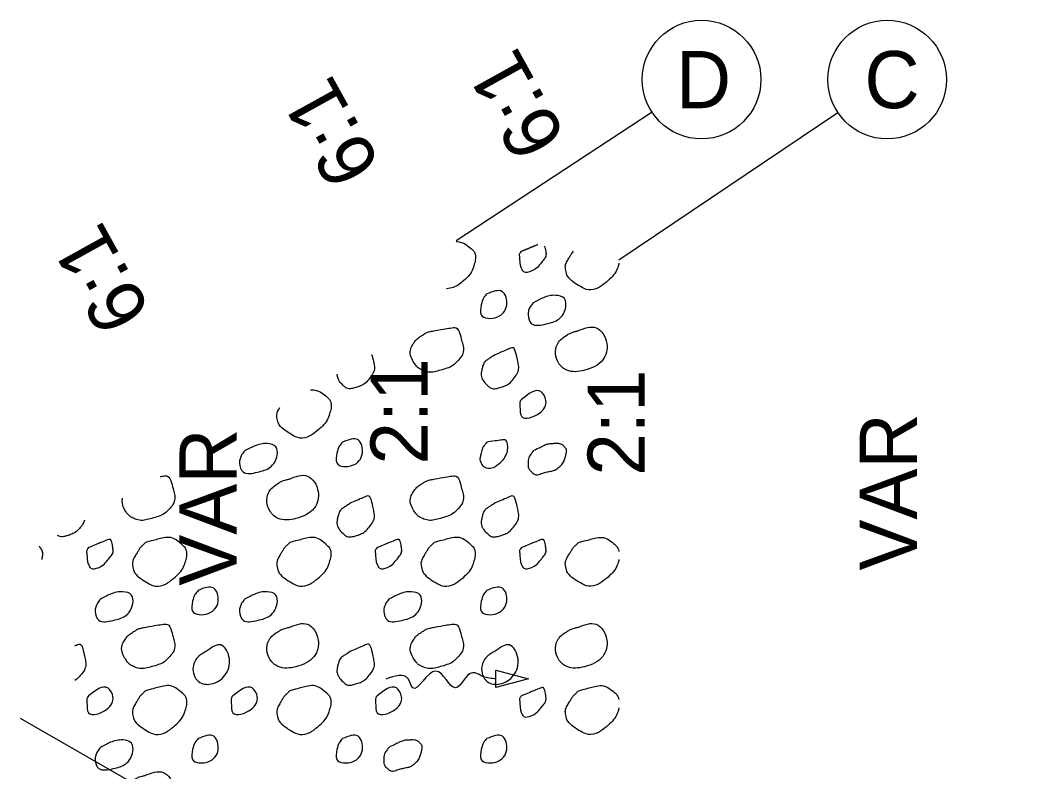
# Model space of a CAD drawing. Extents: x 0 to 2278, y -264 to 330.
# Drawn here: x 275.97 to 313.29, y 222.49 to 250.09 of the extents above; entities that cross this region are included whole.
import ezdxf

# ---------------------------------------------------------------- set-up
doc = ezdxf.new("R2010")
doc.units = 0
for name, color, linetype in [('DR_P_Culvert', 7, 'Continuous'), ('TX_X_10', 7, 'Continuous'), ('XS_P_Finished_Grade', 7, 'Continuous')]:
    doc.layers.add(name, color=color, linetype=linetype)

msp = doc.modelspace()

# ---------------------------------------------------------------- linework, layer by layer
at = {"layer": 'DR_P_Culvert'}
msp.add_line((275.975, 224.45), (325.671, 195.939), dxfattribs=at)
for centre in [(301.013, 247.915), (307.834, 247.915)]:
    msp.add_circle(centre, 2.179, dxfattribs=at)
at = {"layer": 'TX_X_10'}
for p, q in [((299.192, 246.717), (291.996, 241.985)), ((306.026, 246.698), (297.975, 241.284)), ((293.453, 226.221), (294.654, 225.903)), ((293.455, 225.577), (293.453, 226.221)), ((294.654, 225.903), (293.455, 225.577))]:
    msp.add_line(p, q, dxfattribs=at)
msp.add_spline([(293.456, 225.902), (293.408, 225.902), (292.914, 226.013), (292.601, 226.121), (291.967, 225.567), (291.237, 226.184), (290.399, 225.562), (290.228, 225.897), (289.404, 225.885)], degree=3, dxfattribs=at)
at = {"layer": 'XS_P_Finished_Grade'}
for points, degree in [([(291.99, 241.965), (292.16, 241.953), (292.331, 241.883), (292.501, 241.741), (292.703, 241.573), (292.716, 241.324), (292.662, 241.138), (292.595, 240.903), (292.446, 240.68), (292.218, 240.485), (292.05, 240.341), (291.842, 240.249), (291.641, 240.233)], 3), ([(294.391, 241.61), (294.592, 241.692), (294.793, 241.777), (294.994, 241.857)], 2), ([(295.23, 241.811), (295.266, 241.736), (295.287, 241.632), (295.292, 241.571), (295.306, 241.422), (295.192, 241.266), (295.068, 241.118), (294.901, 240.916), (294.48, 240.77), (294.393, 240.991), (294.347, 241.109), (294.34, 241.23), (294.335, 241.351), (294.332, 241.412), (294.31, 241.479), (294.341, 241.533), (294.357, 241.56), (294.375, 241.584), (294.391, 241.61)], 3), ([(297.975, 241.172), (297.972, 241.16), (297.969, 241.149), (297.966, 241.138), (297.899, 240.903), (297.75, 240.68), (297.522, 240.485), (297.237, 240.242), (296.841, 240.146), (296.55, 240.319), (296.313, 240.459), (296.064, 240.669), (296.018, 240.916), (295.99, 241.071), (296.07, 241.25), (296.161, 241.394), (296.207, 241.467), (296.249, 241.54), (296.3, 241.606)], 3), ([(291.155, 238.681), (291.382, 238.72), (291.609, 238.763), (291.836, 238.794), (292.063, 238.826), (292.168, 238.437), (292.225, 238.224), (292.276, 238.031), (292.243, 237.795), (292.08, 237.614), (291.88, 237.393), (291.658, 237.308), (291.411, 237.236), (291.199, 237.173), (290.962, 237.151), (290.751, 237.239), (290.623, 237.293), (290.53, 237.387), (290.452, 237.507), (290.323, 237.708), (290.284, 237.985), (290.397, 238.174), (290.472, 238.3), (290.574, 238.411), (290.705, 238.494), (290.815, 238.565), (290.921, 238.631), (291.043, 238.657), (291.085, 238.666), (291.126, 238.674), (291.167, 238.683)], 3), ([(293.428, 237.807), (293.604, 237.882), (293.78, 237.958), (293.956, 238.033), (294.138, 238.111), (294.227, 237.711), (294.267, 237.526), (294.31, 237.329), (294.259, 237.109), (294.1, 236.918), (293.95, 236.739), (293.779, 236.654), (293.6, 236.599), (293.456, 236.556), (293.274, 236.549), (293.133, 236.688), (292.963, 236.857), (292.899, 237.055), (292.933, 237.227), (292.961, 237.363), (293.024, 237.543), (293.152, 237.628), (293.244, 237.689), (293.337, 237.747), (293.428, 237.807)], 3), ([(288.884, 237.82), (288.921, 237.718), (288.947, 237.603), (288.963, 237.526), (289.006, 237.329), (288.955, 237.109), (288.796, 236.918), (288.646, 236.739), (288.476, 236.654), (288.296, 236.599), (288.152, 236.556), (287.971, 236.549), (287.83, 236.688), (287.702, 236.814), (287.635, 236.956), (287.623, 237.092)], 3), ([(286.635, 236.522), (286.822, 236.52), (287.01, 236.452), (287.197, 236.296), (287.399, 236.127), (287.412, 235.878), (287.358, 235.692), (287.291, 235.457), (287.143, 235.234), (286.915, 235.039), (286.63, 234.796), (286.234, 234.7), (285.942, 234.873), (285.706, 235.013), (285.457, 235.223), (285.411, 235.471), (285.387, 235.598), (285.438, 235.743), (285.508, 235.871)], 3), ([(293.122, 234.594), (293.313, 234.621), (293.504, 234.652), (293.695, 234.677), (293.865, 234.7), (293.905, 234.332), (293.851, 234.185), (293.792, 234.022), (293.644, 233.861), (293.491, 233.744), (293.334, 233.623), (293.002, 233.643), (292.911, 233.829), (292.854, 233.945), (292.882, 234.081), (292.915, 234.197), (292.938, 234.28), (292.948, 234.374), (293.002, 234.442), (293.042, 234.493), (293.082, 234.543), (293.122, 234.594)], 3), ([(294.828, 234.269), (294.953, 234.332), (295.078, 234.394), (295.203, 234.456), (295.341, 234.525), (295.505, 234.538), (295.655, 234.542), (295.765, 234.546), (295.871, 234.52), (295.971, 234.421), (296.062, 234.331), (296.049, 234.211), (296.022, 234.116), (295.978, 233.959), (295.919, 233.798), (295.766, 233.671), (295.616, 233.546), (295.457, 233.529), (295.296, 233.491), (295.127, 233.452), (294.934, 233.352), (294.768, 233.5), (294.659, 233.598), (294.637, 233.712), (294.64, 233.824), (294.642, 233.923), (294.655, 234.041), (294.717, 234.124), (294.754, 234.173), (294.791, 234.221), (294.828, 234.269)], 3), ([(281.109, 233.331), (281.149, 233.337), (281.189, 233.343), (281.229, 233.349), (281.455, 233.38), (281.56, 232.991), (281.617, 232.779), (281.669, 232.585), (281.635, 232.349), (281.472, 232.169), (281.272, 231.947), (281.05, 231.862), (280.804, 231.79), (280.592, 231.728), (280.354, 231.705), (280.144, 231.794), (280.015, 231.848), (279.922, 231.941), (279.845, 232.061), (279.755, 232.2), (279.709, 232.375), (279.726, 232.533)], 3), ([(291.155, 233.235), (291.382, 233.274), (291.609, 233.317), (291.836, 233.349), (292.063, 233.38), (292.168, 232.991), (292.225, 232.779), (292.276, 232.585), (292.243, 232.349), (292.08, 232.169), (291.88, 231.947), (291.658, 231.862), (291.411, 231.79), (291.199, 231.728), (290.962, 231.705), (290.751, 231.794), (290.623, 231.848), (290.53, 231.941), (290.452, 232.061), (290.323, 232.262), (290.284, 232.539), (290.397, 232.729), (290.472, 232.854), (290.574, 232.966), (290.705, 233.049), (290.815, 233.119), (290.921, 233.185), (291.043, 233.211), (291.085, 233.22), (291.126, 233.229), (291.167, 233.237)], 3), ([(288.125, 232.361), (288.301, 232.437), (288.476, 232.512), (288.652, 232.587), (288.835, 232.666), (288.923, 232.266), (288.963, 232.08), (289.006, 231.883), (288.955, 231.663), (288.796, 231.472), (288.646, 231.293), (288.476, 231.208), (288.296, 231.154), (288.152, 231.11), (287.971, 231.103), (287.83, 231.242), (287.659, 231.411), (287.595, 231.609), (287.63, 231.781), (287.657, 231.918), (287.721, 232.098), (287.848, 232.182), (287.94, 232.244), (288.033, 232.301), (288.125, 232.361)], 3), ([(293.428, 232.361), (293.604, 232.437), (293.78, 232.512), (293.956, 232.587), (294.138, 232.666), (294.227, 232.266), (294.267, 232.08), (294.31, 231.883), (294.259, 231.663), (294.1, 231.472), (293.95, 231.293), (293.779, 231.208), (293.6, 231.154), (293.456, 231.11), (293.274, 231.103), (293.133, 231.242), (292.963, 231.411), (292.899, 231.609), (292.933, 231.781), (292.961, 231.918), (293.024, 232.098), (293.152, 232.182), (293.244, 232.244), (293.337, 232.301), (293.428, 232.361)], 3), ([(278.334, 231.729), (278.305, 231.641), (278.257, 231.554), (278.189, 231.472), (278.039, 231.293), (277.868, 231.208), (277.689, 231.154), (277.584, 231.122), (277.46, 231.11), (277.346, 231.159)], 3), ([(278.48, 230.719), (278.717, 230.815), (278.955, 230.917), (279.192, 231.007), (279.309, 231.052), (279.37, 230.792), (279.381, 230.68), (279.395, 230.531), (279.281, 230.374), (279.157, 230.226), (278.99, 230.025), (278.569, 229.879), (278.482, 230.1), (278.436, 230.218), (278.428, 230.339), (278.424, 230.46), (278.421, 230.52), (278.398, 230.587), (278.43, 230.641), (278.446, 230.669), (278.463, 230.693), (278.48, 230.719)], 3), ([(280.579, 230.907), (280.756, 230.955), (280.934, 231.001), (281.112, 231.047), (281.372, 231.115), (281.634, 231.067), (281.894, 230.85), (282.095, 230.681), (282.108, 230.432), (282.055, 230.246), (281.987, 230.011), (281.839, 229.788), (281.611, 229.594), (281.326, 229.35), (280.93, 229.255), (280.639, 229.427), (280.402, 229.567), (280.153, 229.777), (280.107, 230.025), (280.079, 230.179), (280.159, 230.359), (280.25, 230.502), (280.314, 230.605), (280.372, 230.709), (280.457, 230.791), (280.498, 230.83), (280.538, 230.869), (280.579, 230.907)], 3), ([(285.882, 230.907), (286.06, 230.955), (286.238, 231.001), (286.416, 231.047), (286.676, 231.115), (286.937, 231.067), (287.197, 230.85), (287.399, 230.681), (287.412, 230.432), (287.358, 230.246), (287.291, 230.011), (287.143, 229.788), (286.915, 229.594), (286.63, 229.35), (286.234, 229.255), (285.942, 229.427), (285.706, 229.567), (285.457, 229.777), (285.411, 230.025), (285.383, 230.179), (285.463, 230.359), (285.553, 230.502), (285.618, 230.605), (285.676, 230.709), (285.761, 230.791), (285.801, 230.83), (285.842, 230.869), (285.882, 230.907)], 3), ([(289.087, 230.719), (289.325, 230.815), (289.562, 230.917), (289.8, 231.007), (289.916, 231.052), (289.978, 230.792), (289.988, 230.68), (290.003, 230.531), (289.888, 230.374), (289.765, 230.226), (289.597, 230.025), (289.177, 229.879), (289.09, 230.1), (289.044, 230.218), (289.036, 230.339), (289.031, 230.46), (289.029, 230.52), (289.006, 230.587), (289.037, 230.641), (289.053, 230.669), (289.071, 230.693), (289.087, 230.719)], 3), ([(291.186, 230.907), (291.364, 230.955), (291.542, 231.001), (291.72, 231.047), (291.98, 231.115), (292.241, 231.067), (292.501, 230.85), (292.703, 230.681), (292.716, 230.432), (292.662, 230.246), (292.595, 230.011), (292.446, 229.788), (292.218, 229.594), (291.933, 229.35), (291.538, 229.255), (291.246, 229.427), (291.01, 229.567), (290.76, 229.777), (290.715, 230.025), (290.686, 230.179), (290.767, 230.359), (290.857, 230.502), (290.922, 230.605), (290.979, 230.709), (291.065, 230.791), (291.105, 230.83), (291.145, 230.869), (291.186, 230.907)], 3), ([(294.391, 230.719), (294.629, 230.815), (294.866, 230.917), (295.103, 231.007), (295.22, 231.052), (295.282, 230.792), (295.292, 230.68), (295.306, 230.531), (295.192, 230.374), (295.068, 230.226), (294.901, 230.025), (294.48, 229.879), (294.393, 230.1), (294.347, 230.218), (294.34, 230.339), (294.335, 230.46), (294.332, 230.52), (294.31, 230.587), (294.341, 230.641), (294.357, 230.669), (294.375, 230.693), (294.391, 230.719)], 3), ([(296.49, 230.907), (296.667, 230.955), (296.846, 231.001), (297.023, 231.047), (297.283, 231.115), (297.545, 231.067), (297.805, 230.85), (297.897, 230.773), (297.95, 230.678), (297.975, 230.581)], 3), ([(276.669, 230.768), (276.784, 230.619), (276.795, 230.435), (276.761, 230.284)], 2), ([(297.975, 230.281), (297.972, 230.269), (297.969, 230.258), (297.966, 230.246), (297.899, 230.011), (297.75, 229.788), (297.522, 229.594), (297.237, 229.35), (296.841, 229.255), (296.55, 229.427), (296.313, 229.567), (296.064, 229.777), (296.018, 230.025), (295.99, 230.179), (296.07, 230.359), (296.161, 230.502), (296.226, 230.605), (296.283, 230.709), (296.368, 230.791), (296.409, 230.83), (296.449, 230.869), (296.49, 230.907)], 3), ([(280.547, 227.789), (280.774, 227.828), (281.002, 227.871), (281.229, 227.903), (281.455, 227.935), (281.56, 227.546), (281.617, 227.333), (281.669, 227.14), (281.635, 226.903), (281.472, 226.723), (281.272, 226.502), (281.05, 226.417), (280.804, 226.344), (280.592, 226.282), (280.354, 226.259), (280.144, 226.348), (280.015, 226.402), (279.922, 226.495), (279.845, 226.615), (279.715, 226.816), (279.677, 227.093), (279.79, 227.283), (279.865, 227.409), (279.967, 227.52), (280.097, 227.603), (280.208, 227.673), (280.313, 227.739), (280.436, 227.765), (280.477, 227.774), (280.519, 227.783), (280.56, 227.792)], 3), ([(291.155, 227.789), (291.382, 227.828), (291.609, 227.871), (291.836, 227.903), (292.063, 227.935), (292.168, 227.546), (292.225, 227.333), (292.276, 227.14), (292.243, 226.903), (292.08, 226.723), (291.88, 226.502), (291.658, 226.417), (291.411, 226.344), (291.199, 226.282), (290.962, 226.259), (290.751, 226.348), (290.623, 226.402), (290.53, 226.495), (290.452, 226.615), (290.323, 226.816), (290.284, 227.093), (290.397, 227.283), (290.472, 227.409), (290.574, 227.52), (290.705, 227.603), (290.815, 227.673), (290.921, 227.739), (291.043, 227.765), (291.085, 227.774), (291.126, 227.783), (291.167, 227.792)], 3), ([(277.975, 227.112), (277.998, 227.122), (278.021, 227.132), (278.045, 227.142), (278.227, 227.22), (278.316, 226.82), (278.356, 226.634), (278.398, 226.438), (278.347, 226.217), (278.189, 226.027), (278.121, 225.946), (278.05, 225.884), (277.975, 225.836)], 3), ([(288.125, 226.915), (288.301, 226.991), (288.476, 227.066), (288.652, 227.142), (288.835, 227.22), (288.923, 226.82), (288.963, 226.634), (289.006, 226.438), (288.955, 226.217), (288.796, 226.027), (288.646, 225.847), (288.476, 225.762), (288.296, 225.708), (288.152, 225.664), (287.971, 225.657), (287.83, 225.797), (287.659, 225.965), (287.595, 226.164), (287.63, 226.335), (287.657, 226.472), (287.721, 226.652), (287.848, 226.737), (287.94, 226.798), (288.033, 226.856), (288.125, 226.915)], 3), ([(280.579, 225.462), (280.756, 225.509), (280.934, 225.556), (281.112, 225.602), (281.372, 225.669), (281.634, 225.621), (281.894, 225.404), (282.095, 225.236), (282.108, 224.987), (282.055, 224.8), (281.987, 224.565), (281.839, 224.343), (281.611, 224.148), (281.326, 223.905), (280.93, 223.809), (280.639, 223.982), (280.402, 224.122), (280.153, 224.332), (280.107, 224.579), (280.079, 224.734), (280.159, 224.913), (280.25, 225.057), (280.314, 225.159), (280.372, 225.263), (280.457, 225.345), (280.498, 225.384), (280.538, 225.423), (280.579, 225.462)], 3), ([(285.882, 225.462), (286.06, 225.509), (286.238, 225.556), (286.416, 225.602), (286.676, 225.669), (286.937, 225.621), (287.197, 225.404), (287.399, 225.236), (287.412, 224.987), (287.358, 224.8), (287.291, 224.565), (287.143, 224.343), (286.915, 224.148), (286.63, 223.905), (286.234, 223.809), (285.942, 223.982), (285.706, 224.122), (285.457, 224.332), (285.411, 224.579), (285.383, 224.734), (285.463, 224.913), (285.553, 225.057), (285.618, 225.159), (285.676, 225.263), (285.761, 225.345), (285.801, 225.384), (285.842, 225.423), (285.882, 225.462)], 3), ([(294.391, 225.273), (294.629, 225.369), (294.866, 225.471), (295.103, 225.562), (295.22, 225.606), (295.282, 225.346), (295.292, 225.234), (295.306, 225.085), (295.192, 224.929), (295.068, 224.78), (294.901, 224.579), (294.48, 224.433), (294.393, 224.654), (294.347, 224.772), (294.34, 224.893), (294.335, 225.014), (294.332, 225.075), (294.31, 225.141), (294.341, 225.195), (294.357, 225.223), (294.375, 225.247), (294.391, 225.273)], 3), ([(297.975, 224.835), (297.972, 224.823), (297.969, 224.812), (297.966, 224.8), (297.899, 224.565), (297.75, 224.343), (297.522, 224.148), (297.237, 223.905), (296.841, 223.809), (296.55, 223.982), (296.313, 224.122), (296.064, 224.332), (296.018, 224.579), (295.99, 224.734), (296.07, 224.913), (296.161, 225.057), (296.226, 225.159), (296.283, 225.263), (296.368, 225.345), (296.409, 225.384), (296.449, 225.423), (296.49, 225.462)], 3), ([(296.49, 225.462), (296.667, 225.509), (296.846, 225.556), (297.023, 225.602), (297.283, 225.669), (297.545, 225.621), (297.805, 225.404), (297.897, 225.327), (297.95, 225.233), (297.975, 225.135)], 3), ([(289.525, 223.377), (289.65, 223.44), (289.774, 223.502), (289.9, 223.565), (290.037, 223.633), (290.201, 223.647), (290.351, 223.651), (290.461, 223.654), (290.568, 223.628), (290.667, 223.53), (290.758, 223.44), (290.745, 223.32), (290.718, 223.225), (290.674, 223.067), (290.615, 222.907), (290.462, 222.78), (290.312, 222.655), (290.153, 222.637), (289.992, 222.6), (289.823, 222.56), (289.63, 222.46), (289.465, 222.608), (289.356, 222.706), (289.333, 222.821), (289.336, 222.932), (289.339, 223.032), (289.351, 223.149), (289.413, 223.232), (289.45, 223.281), (289.487, 223.329), (289.525, 223.377)], 3)]:
    msp.add_open_spline(points, degree=degree, dxfattribs=at)
for points in [[(293.122, 240.039), (293.695, 240.123), (293.851, 239.631), (293.491, 239.189), (292.911, 239.274), (292.915, 239.643), (293.002, 239.888), (293.122, 240.039)], [(294.828, 239.714), (295.203, 239.902), (295.655, 239.988), (295.971, 239.867), (296.022, 239.562), (295.766, 239.117), (295.296, 238.937), (294.768, 238.946), (294.64, 239.269), (294.717, 239.569), (294.828, 239.714)], [(296.458, 238.681), (297.14, 238.794), (297.528, 238.224), (297.383, 237.614), (296.715, 237.236), (296.055, 237.239), (295.756, 237.507), (295.701, 238.174), (296.008, 238.494), (296.347, 238.657), (296.471, 238.683)], [(294.391, 236.164), (295.103, 236.453), (295.292, 236.126), (295.068, 235.672), (294.393, 235.546), (294.335, 235.906), (294.341, 236.087), (294.391, 236.164)], [(287.818, 234.594), (288.391, 234.677), (288.547, 234.185), (288.187, 233.744), (287.607, 233.829), (287.611, 234.197), (287.698, 234.442), (287.818, 234.594)], [(284.221, 234.269), (284.596, 234.456), (285.047, 234.542), (285.363, 234.421), (285.415, 234.116), (285.158, 233.671), (284.688, 233.491), (284.161, 233.5), (284.032, 233.824), (284.11, 234.124), (284.221, 234.269)], [(285.851, 233.235), (286.532, 233.349), (286.921, 232.779), (286.776, 232.169), (286.107, 231.79), (285.447, 231.794), (285.148, 232.061), (285.093, 232.729), (285.401, 233.049), (285.74, 233.211), (285.863, 233.237)], [(282.515, 229.148), (283.087, 229.232), (283.244, 228.739), (282.884, 228.298), (282.304, 228.383), (282.307, 228.752), (282.395, 228.997), (282.515, 229.148)], [(293.122, 229.148), (293.695, 229.232), (293.851, 228.739), (293.491, 228.298), (292.911, 228.383), (292.915, 228.752), (293.002, 228.997), (293.122, 229.148)], [(278.917, 228.823), (279.292, 229.01), (279.744, 229.097), (280.06, 228.975), (280.111, 228.67), (279.855, 228.225), (279.385, 228.045), (278.857, 228.054), (278.729, 228.378), (278.806, 228.678), (278.917, 228.823)], [(284.221, 228.823), (284.596, 229.01), (285.047, 229.097), (285.363, 228.975), (285.415, 228.67), (285.158, 228.225), (284.688, 228.045), (284.161, 228.054), (284.032, 228.378), (284.11, 228.678), (284.221, 228.823)], [(289.525, 228.823), (289.9, 229.01), (290.351, 229.097), (290.667, 228.975), (290.718, 228.67), (290.462, 228.225), (289.992, 228.045), (289.465, 228.054), (289.336, 228.378), (289.413, 228.678), (289.525, 228.823)], [(285.851, 227.789), (286.532, 227.903), (286.921, 227.333), (286.776, 226.723), (286.107, 226.344), (285.447, 226.348), (285.148, 226.615), (285.093, 227.283), (285.401, 227.603), (285.74, 227.765), (285.863, 227.792)], [(296.458, 227.789), (297.14, 227.903), (297.528, 227.333), (297.383, 226.723), (296.715, 226.344), (296.055, 226.348), (295.756, 226.615), (295.701, 227.283), (296.008, 227.603), (296.347, 227.765), (296.471, 227.792)], [(282.821, 226.915), (283.349, 227.142), (283.66, 226.634), (283.492, 226.027), (282.992, 225.708), (282.526, 225.797), (282.326, 226.335), (282.545, 226.737), (282.821, 226.915)], [(293.428, 226.915), (293.956, 227.142), (294.267, 226.634), (294.1, 226.027), (293.6, 225.708), (293.133, 225.797), (292.933, 226.335), (293.152, 226.737), (293.428, 226.915)], [(278.48, 225.273), (279.192, 225.562), (279.381, 225.234), (279.157, 224.78), (278.482, 224.654), (278.424, 225.014), (278.43, 225.195), (278.48, 225.273)], [(283.783, 225.273), (284.496, 225.562), (284.685, 225.234), (284.461, 224.78), (283.786, 224.654), (283.727, 225.014), (283.733, 225.195), (283.783, 225.273)], [(289.087, 225.273), (289.8, 225.562), (289.988, 225.234), (289.765, 224.78), (289.09, 224.654), (289.031, 225.014), (289.037, 225.195), (289.087, 225.273)], [(278.917, 223.377), (279.292, 223.565), (279.744, 223.651), (280.06, 223.53), (280.111, 223.225), (279.855, 222.78), (279.385, 222.6), (278.857, 222.608), (278.729, 222.932), (278.806, 223.232), (278.917, 223.377)], [(282.515, 223.702), (283.087, 223.786), (283.244, 223.293), (282.884, 222.852), (282.304, 222.937), (282.307, 223.306), (282.395, 223.551), (282.515, 223.702)], [(287.818, 223.702), (288.391, 223.786), (288.547, 223.293), (288.187, 222.852), (287.607, 222.937), (287.611, 223.306), (287.698, 223.551), (287.818, 223.702)], [(293.122, 223.702), (293.695, 223.786), (293.851, 223.293), (293.491, 222.852), (292.911, 222.937), (292.915, 223.306), (293.002, 223.551), (293.122, 223.702)], [(280.547, 222.343), (281.229, 222.457), (281.617, 221.887), (281.472, 221.277), (280.804, 220.898), (280.144, 220.902), (279.845, 221.17), (279.79, 221.837), (280.097, 222.157), (280.436, 222.32), (280.56, 222.346)]]:
    msp.add_spline(points, degree=3, dxfattribs=at)

# ---------------------------------------------------------------- texts
at = {"layer": 'DR_P_Culvert'}
for s, rotation, p in [('6:1', 118.9986, (296.075, 245.77)), ('6:1', 118.9986, (289.264, 244.748)), ('6:1', 118.9986, (280.815, 239.365)), ('2:1', 90, (290.946, 233.769)), ('2:1', 90, (298.925, 233.362)), ('VAR', 90, (308.925, 229.877)), ('VAR', 90, (283.925, 229.32))]:
    msp.add_text(s, height=2.1, rotation=rotation, dxfattribs=at).set_placement(p)
for s, p in [('D', (300.07, 246.865)), ('C', (306.997, 246.865))]:
    msp.add_text(s, height=2.1, dxfattribs=at).set_placement(p)

doc.saveas('drawing.dxf')
